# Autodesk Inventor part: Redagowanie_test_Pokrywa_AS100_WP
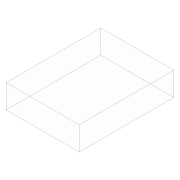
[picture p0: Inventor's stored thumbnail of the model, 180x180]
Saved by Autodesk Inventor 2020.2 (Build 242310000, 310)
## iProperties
Created: 2015-11
Part Number: Redagowanie_test_Pokrywa_AS100_WP
Material: Ogólne
Document SubType Name: Modeling
Designer: F.Stasiak
Density: 1 g/cm^3
Appearance: Domyślne
Catalog Web Link: www.expertbooks.pl
Manager: www.cadconsulting.pl
Company: Fabian Stasiak CAD Consulting
d1: 54,000 mm
d2: 54,000 mm
d3: 70,000 mm
d4: 70,000 mm
d5: 35,000 mm
d6: 0,00 deg
Xmin: -54,000 mm
Ymin: -70,000 mm
Zmin: -19,000 mm
Xmax: 54,000 mm
Ymax: 70,000 mm
Zmax: 16,000 mm
Author: F.Stasiak
Subject: Zbiór ćwiczeń. Autodesk Inventor 2020. Kurs Professional
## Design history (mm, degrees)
sketch "Szkic1"
  geometry: L1 (-54, 70)-(54, 70); L2 (54, 70)-(54, -70); L3 (54, -70)-(-54, -70); L4 (-54, -70)-(-54, 70); 1 further point
  constraints: 8 end point, 2 parallel, 1 horizontal, 1 perpendicular, 1 other
  dimensions: "d1" = 54 distance from line of L4 point (0, 0) (= -Xmin); "d2" = 54 distance from line of L2 point (0, 0) (= Xmax); "d3" = 70 distance from line of L3 point (0, 0) (= -Ymin); "d4" = 70 distance from line of L1 point (0, 0) (= Ymax)
extrude "Wyciągnięcie proste1" join sketch "Szkic1" distance "d5" = 35 (= Zmax - Zmin); taper "d6" = 0 deg
node "Bryła1"
other parameters: "Xmin" = -54 [user parameter; used in 1 equation term], "Ymin" = -70 [user parameter; used in 1 equation term], "Zmin" = -19 [user parameter; used in 1 equation term], "Xmax" = 54 [user parameter; used in 1 equation term], "Ymax" = 70 [user parameter; used in 1 equation term], "Zmax" = 16 [user parameter; used in 1 equation term], "d8" = -18
